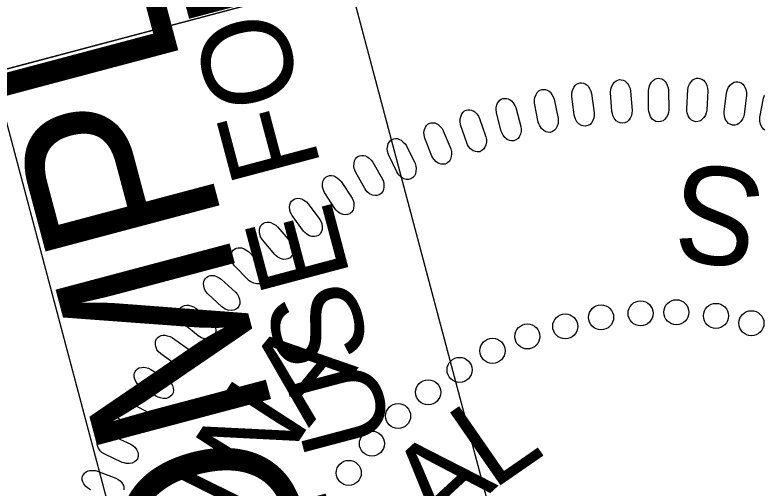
# Model space of a CAD drawing. Extents: x 473963 to 475454, y 503101 to 505009.
# Drawn here: x 474084.44 to 474132.36, y 504611.93 to 504642.22 of the extents above; entities that cross this region are included whole.
import ezdxf

# ---------------------------------------------------------------- set-up
doc = ezdxf.new("R2010")
doc.units = 0
for name, color, linetype in [('Prop PHM Label Text', 7, 'Continuous'), ('Scratch_Level_2', 7, 'Continuous'), ('Scratch_Level_4', 7, 'Continuous')]:
    doc.layers.add(name, color=color, linetype=linetype)

msp = doc.modelspace()

# ---------------------------------------------------------------- linework, layer by layer
at = {"layer": 'Prop PHM Label Text'}
msp.add_line((474051.4, 504630.133), (474160.089, 504659.021), dxfattribs=at)
for points in [[(474051.4, 504630.133), (474025.716, 504726.765), (474134.453, 504755.666), (474160.141, 504659.021)], [(474077.089, 504533.437), (474051.4, 504630.133), (474160.141, 504659.021), (474185.802, 504562.331)]]:
    msp.add_lwpolyline(points, close=True, dxfattribs=at)
at = {"layer": 'Scratch_Level_2'}
msp.add_lwpolyline([(474124.636, 504573.539), (474101.924, 504567.506), (474064.181, 504709.577), (474086.893, 504715.611)], close=True, dxfattribs=at)
at = {"layer": 'Scratch_Level_4'}
for points in [[(474122.636, 504636.032), (474122.549, 504637.256), (474122.571, 504637.477), (474122.612, 504637.62), (474122.713, 504637.798), (474122.802, 504637.914), (474122.908, 504638.002), (474123.01, 504638.049), (474123.12, 504638.077), (474123.233, 504638.065), (474123.355, 504638.043), (474123.464, 504637.991), (474123.575, 504637.898), (474123.641, 504637.823), (474123.718, 504637.679), (474123.79, 504637.504), (474123.824, 504637.347), (474123.921, 504636.094), (474123.91, 504635.923), (474123.875, 504635.781), (474123.797, 504635.615), (474123.695, 504635.468), (474123.604, 504635.381), (474123.451, 504635.311), (474123.303, 504635.28), (474123.152, 504635.309), (474123.044, 504635.352), (474122.91, 504635.442), (474122.779, 504635.603), (474122.699, 504635.777), (474122.661, 504635.904)], [(474124.982, 504636.158), (474124.972, 504637.385), (474125.008, 504637.604), (474125.058, 504637.744), (474125.169, 504637.915), (474125.266, 504638.025), (474125.378, 504638.106), (474125.481, 504638.146), (474125.593, 504638.167), (474125.705, 504638.149), (474125.826, 504638.119), (474125.931, 504638.061), (474126.036, 504637.961), (474126.097, 504637.882), (474126.165, 504637.733), (474126.226, 504637.554), (474126.25, 504637.395), (474126.268, 504636.138), (474126.246, 504635.968), (474126.203, 504635.828), (474126.115, 504635.668), (474126.003, 504635.528), (474125.907, 504635.447), (474125.75, 504635.386), (474125.601, 504635.365), (474125.451, 504635.403), (474125.346, 504635.453), (474125.218, 504635.551), (474125.097, 504635.72), (474125.028, 504635.899), (474124.998, 504636.028)], [(474127.416, 504636.212), (474127.483, 504637.437), (474127.533, 504637.654), (474127.592, 504637.791), (474127.714, 504637.954), (474127.816, 504638.058), (474127.933, 504638.132), (474128.04, 504638.166), (474128.152, 504638.179), (474128.263, 504638.153), (474128.382, 504638.116), (474128.482, 504638.052), (474128.581, 504637.946), (474128.637, 504637.863), (474128.695, 504637.71), (474128.746, 504637.528), (474128.76, 504637.367), (474128.698, 504636.112), (474128.666, 504635.944), (474128.613, 504635.807), (474128.516, 504635.652), (474128.396, 504635.519), (474128.295, 504635.445), (474128.135, 504635.394), (474127.983, 504635.382), (474127.837, 504635.43), (474127.735, 504635.486), (474127.614, 504635.592), (474127.504, 504635.768), (474127.446, 504635.951), (474127.424, 504636.082)], [(474120.227, 504635.803), (474120.064, 504637.019), (474120.071, 504637.241), (474120.104, 504637.387), (474120.193, 504637.57), (474120.275, 504637.692), (474120.375, 504637.785), (474120.473, 504637.839), (474120.582, 504637.873), (474120.695, 504637.869), (474120.818, 504637.855), (474120.93, 504637.81), (474121.047, 504637.725), (474121.117, 504637.654), (474121.204, 504637.514), (474121.286, 504637.345), (474121.33, 504637.189), (474121.505, 504635.945), (474121.505, 504635.773), (474121.479, 504635.629), (474121.412, 504635.46), (474121.319, 504635.306), (474121.234, 504635.214), (474121.086, 504635.134), (474120.941, 504635.094), (474120.787, 504635.114), (474120.677, 504635.149), (474120.537, 504635.231), (474120.397, 504635.383), (474120.305, 504635.552), (474120.259, 504635.677)], [(474129.823, 504636.023), (474129.967, 504637.241), (474130.03, 504637.454), (474130.098, 504637.587), (474130.23, 504637.743), (474130.339, 504637.84), (474130.46, 504637.906), (474130.568, 504637.933), (474130.682, 504637.94), (474130.791, 504637.907), (474130.906, 504637.863), (474131.003, 504637.792), (474131.096, 504637.68), (474131.146, 504637.593), (474131.195, 504637.437), (474131.233, 504637.252), (474131.237, 504637.091), (474131.096, 504635.842), (474131.054, 504635.676), (474130.993, 504635.543), (474130.885, 504635.395), (474130.758, 504635.269), (474130.652, 504635.201), (474130.489, 504635.161), (474130.338, 504635.158), (474130.194, 504635.216), (474130.096, 504635.278), (474129.982, 504635.391), (474129.884, 504635.574), (474129.837, 504635.761), (474129.823, 504635.892)], [(474117.923, 504635.363), (474117.683, 504636.567), (474117.677, 504636.788), (474117.701, 504636.936), (474117.778, 504637.125), (474117.852, 504637.251), (474117.946, 504637.351), (474118.041, 504637.41), (474118.148, 504637.452), (474118.261, 504637.454), (474118.384, 504637.448), (474118.498, 504637.41), (474118.62, 504637.332), (474118.695, 504637.266), (474118.79, 504637.132), (474118.884, 504636.968), (474118.937, 504636.816), (474119.19, 504635.585), (474119.201, 504635.415), (474119.183, 504635.268), (474119.127, 504635.095), (474119.044, 504634.936), (474118.965, 504634.838), (474118.822, 504634.749), (474118.679, 504634.7), (474118.525, 504634.71), (474118.413, 504634.739), (474118.269, 504634.812), (474118.118, 504634.955), (474118.017, 504635.118), (474117.963, 504635.239)], [(474115.555, 504634.769), (474115.241, 504635.955), (474115.221, 504636.176), (474115.235, 504636.324), (474115.3, 504636.517), (474115.366, 504636.648), (474115.454, 504636.754), (474115.545, 504636.819), (474115.649, 504636.867), (474115.762, 504636.877), (474115.885, 504636.878), (474116.001, 504636.847), (474116.128, 504636.778), (474116.207, 504636.716), (474116.31, 504636.589), (474116.414, 504636.431), (474116.476, 504636.282), (474116.806, 504635.069), (474116.828, 504634.9), (474116.82, 504634.753), (474116.774, 504634.576), (474116.702, 504634.413), (474116.628, 504634.31), (474116.492, 504634.212), (474116.352, 504634.155), (474116.198, 504634.155), (474116.084, 504634.176), (474115.935, 504634.24), (474115.777, 504634.374), (474115.665, 504634.53), (474115.603, 504634.647)], [(474113.341, 504634.026), (474112.954, 504635.19), (474112.92, 504635.41), (474112.924, 504635.558), (474112.977, 504635.755), (474113.035, 504635.89), (474113.116, 504636.001), (474113.203, 504636.071), (474113.303, 504636.126), (474113.415, 504636.143), (474113.538, 504636.152), (474113.656, 504636.129), (474113.787, 504636.067), (474113.869, 504636.01), (474113.981, 504635.89), (474114.094, 504635.739), (474114.166, 504635.595), (474114.571, 504634.405), (474114.603, 504634.237), (474114.604, 504634.09), (474114.57, 504633.91), (474114.508, 504633.743), (474114.441, 504633.636), (474114.311, 504633.53), (474114.175, 504633.463), (474114.021, 504633.454), (474113.906, 504633.468), (474113.754, 504633.523), (474113.587, 504633.645), (474113.466, 504633.794), (474113.397, 504633.908)], [(474111.119, 504633.184), (474110.658, 504634.321), (474110.61, 504634.538), (474110.606, 504634.687), (474110.646, 504634.886), (474110.695, 504635.025), (474110.769, 504635.141), (474110.851, 504635.217), (474110.947, 504635.277), (474111.059, 504635.301), (474111.181, 504635.318), (474111.301, 504635.302), (474111.435, 504635.249), (474111.52, 504635.198), (474111.639, 504635.084), (474111.762, 504634.94), (474111.843, 504634.801), (474112.322, 504633.639), (474112.364, 504633.473), (474112.375, 504633.327), (474112.352, 504633.146), (474112.3, 504632.974), (474112.24, 504632.863), (474112.118, 504632.749), (474111.986, 504632.674), (474111.833, 504632.655), (474111.717, 504632.663), (474111.562, 504632.707), (474111.387, 504632.819), (474111.258, 504632.96), (474111.181, 504633.07)], [(474108.863, 504632.173), (474108.332, 504633.278), (474108.271, 504633.492), (474108.257, 504633.641), (474108.285, 504633.842), (474108.325, 504633.983), (474108.392, 504634.104), (474108.469, 504634.185), (474108.561, 504634.252), (474108.671, 504634.282), (474108.792, 504634.306), (474108.912, 504634.298), (474109.049, 504634.253), (474109.138, 504634.208), (474109.264, 504634.102), (474109.395, 504633.966), (474109.484, 504633.832), (474110.035, 504632.702), (474110.088, 504632.539), (474110.108, 504632.395), (474110.096, 504632.212), (474110.056, 504632.038), (474110.003, 504631.924), (474109.887, 504631.801), (474109.761, 504631.719), (474109.609, 504631.69), (474109.494, 504631.69), (474109.336, 504631.724), (474109.155, 504631.826), (474109.015, 504631.959), (474108.933, 504632.062)], [(474106.815, 504631.101), (474106.217, 504632.171), (474106.142, 504632.38), (474106.119, 504632.528), (474106.133, 504632.731), (474106.165, 504632.875), (474106.224, 504632.999), (474106.295, 504633.084), (474106.384, 504633.157), (474106.491, 504633.195), (474106.61, 504633.227), (474106.73, 504633.226), (474106.871, 504633.19), (474106.962, 504633.149), (474107.093, 504633.052), (474107.234, 504632.924), (474107.331, 504632.796), (474107.952, 504631.704), (474108.015, 504631.545), (474108.044, 504631.401), (474108.044, 504631.218), (474108.015, 504631.042), (474107.969, 504630.924), (474107.861, 504630.795), (474107.74, 504630.705), (474107.59, 504630.667), (474107.475, 504630.659), (474107.315, 504630.684), (474107.128, 504630.773), (474106.982, 504630.897), (474106.892, 504630.996)], [(474104.907, 504629.823), (474104.241, 504630.854), (474104.153, 504631.059), (474104.121, 504631.204), (474104.124, 504631.407), (474104.145, 504631.552), (474104.197, 504631.68), (474104.263, 504631.77), (474104.346, 504631.848), (474104.451, 504631.892), (474104.568, 504631.932), (474104.688, 504631.938), (474104.83, 504631.911), (474104.924, 504631.877), (474105.062, 504631.787), (474105.209, 504631.67), (474105.315, 504631.548), (474106.003, 504630.496), (474106.076, 504630.342), (474106.113, 504630.2), (474106.125, 504630.017), (474106.107, 504629.839), (474106.068, 504629.719), (474105.969, 504629.583), (474105.854, 504629.486), (474105.707, 504629.438), (474105.592, 504629.424), (474105.431, 504629.438), (474105.239, 504629.515), (474105.085, 504629.63), (474104.989, 504629.723)], [(474102.894, 504628.384), (474102.165, 504629.371), (474102.065, 504629.57), (474102.024, 504629.713), (474102.013, 504629.916), (474102.027, 504630.062), (474102.069, 504630.193), (474102.13, 504630.287), (474102.208, 504630.37), (474102.311, 504630.42), (474102.424, 504630.467), (474102.544, 504630.481), (474102.688, 504630.463), (474102.783, 504630.435), (474102.926, 504630.354), (474103.081, 504630.246), (474103.193, 504630.131), (474103.946, 504629.124), (474104.029, 504628.975), (474104.076, 504628.836), (474104.098, 504628.654), (474104.092, 504628.475), (474104.061, 504628.353), (474103.97, 504628.211), (474103.861, 504628.107), (474103.718, 504628.05), (474103.604, 504628.028), (474103.442, 504628.032), (474103.245, 504628.098), (474103.084, 504628.202), (474102.984, 504628.289)], [(474101.057, 504626.883), (474100.268, 504627.822), (474100.155, 504628.014), (474100.105, 504628.154), (474100.082, 504628.356), (474100.086, 504628.503), (474100.12, 504628.636), (474100.175, 504628.734), (474100.248, 504628.821), (474100.346, 504628.878), (474100.457, 504628.932), (474100.576, 504628.954), (474100.72, 504628.945), (474100.817, 504628.922), (474100.965, 504628.851), (474101.126, 504628.752), (474101.246, 504628.644), (474102.061, 504627.687), (474102.152, 504627.543), (474102.208, 504627.407), (474102.242, 504627.228), (474102.246, 504627.048), (474102.223, 504626.925), (474102.141, 504626.778), (474102.04, 504626.666), (474101.9, 504626.601), (474101.787, 504626.572), (474101.626, 504626.566), (474101.425, 504626.619), (474101.258, 504626.713), (474101.152, 504626.794)], [(474099.328, 504625.278), (474098.481, 504626.165), (474098.357, 504626.35), (474098.298, 504626.486), (474098.262, 504626.687), (474098.257, 504626.833), (474098.283, 504626.969), (474098.332, 504627.07), (474098.399, 504627.161), (474098.494, 504627.224), (474098.601, 504627.285), (474098.717, 504627.315), (474098.862, 504627.315), (474098.96, 504627.298), (474099.113, 504627.236), (474099.28, 504627.147), (474099.406, 504627.048), (474100.279, 504626.144), (474100.38, 504626.005), (474100.444, 504625.873), (474100.489, 504625.696), (474100.504, 504625.518), (474100.489, 504625.393), (474100.417, 504625.241), (474100.322, 504625.124), (474100.187, 504625.049), (474100.077, 504625.013), (474099.916, 504624.997), (474099.712, 504625.038), (474099.539, 504625.121), (474099.428, 504625.194)], [(474097.671, 504623.533), (474096.77, 504624.365), (474096.634, 504624.542), (474096.567, 504624.675), (474096.518, 504624.872), (474096.504, 504625.018), (474096.521, 504625.154), (474096.563, 504625.259), (474096.625, 504625.354), (474096.715, 504625.423), (474096.819, 504625.491), (474096.933, 504625.527), (474097.078, 504625.536), (474097.177, 504625.526), (474097.333, 504625.473), (474097.505, 504625.396), (474097.637, 504625.304), (474098.565, 504624.457), (474098.674, 504624.325), (474098.746, 504624.197), (474098.803, 504624.023), (474098.829, 504623.846), (474098.822, 504623.72), (474098.76, 504623.565), (474098.673, 504623.442), (474098.542, 504623.359), (474098.434, 504623.316), (474098.274, 504623.29), (474098.069, 504623.317), (474097.891, 504623.39), (474097.776, 504623.456)], [(474096.15, 504621.679), (474095.199, 504622.454), (474095.052, 504622.621), (474094.976, 504622.75), (474094.916, 504622.944), (474094.892, 504623.089), (474094.901, 504623.226), (474094.936, 504623.332), (474094.991, 504623.432), (474095.078, 504623.506), (474095.176, 504623.58), (474095.289, 504623.624), (474095.432, 504623.642), (474095.532, 504623.638), (474095.691, 504623.595), (474095.867, 504623.529), (474096.005, 504623.446), (474096.985, 504622.658), (474097.101, 504622.534), (474097.182, 504622.41), (474097.249, 504622.24), (474097.286, 504622.065), (474097.287, 504621.939), (474097.234, 504621.78), (474097.156, 504621.651), (474097.03, 504621.561), (474096.926, 504621.511), (474096.768, 504621.475), (474096.561, 504621.489), (474096.379, 504621.55), (474096.26, 504621.609)], [(474094.763, 504619.8), (474093.765, 504620.513), (474093.608, 504620.672), (474093.525, 504620.795), (474093.452, 504620.985), (474093.42, 504621.128), (474093.42, 504621.265), (474093.448, 504621.374), (474093.497, 504621.477), (474093.579, 504621.556), (474093.673, 504621.636), (474093.782, 504621.687), (474093.924, 504621.714), (474094.024, 504621.716), (474094.185, 504621.683), (474094.365, 504621.628), (474094.508, 504621.554), (474095.535, 504620.829), (474095.66, 504620.712), (474095.748, 504620.594), (474095.825, 504620.429), (474095.874, 504620.256), (474095.882, 504620.131), (474095.84, 504619.968), (474095.769, 504619.835), (474095.649, 504619.737), (474095.548, 504619.681), (474095.393, 504619.635), (474095.186, 504619.636), (474095, 504619.686), (474094.877, 504619.737)], [(474093.489, 504617.794), (474092.449, 504618.443), (474092.283, 504618.591), (474092.191, 504618.709), (474092.107, 504618.894), (474092.065, 504619.034), (474092.057, 504619.171), (474092.078, 504619.282), (474092.12, 504619.388), (474092.197, 504619.472), (474092.286, 504619.558), (474092.391, 504619.615), (474092.531, 504619.651), (474092.631, 504619.659), (474092.793, 504619.637), (474092.977, 504619.593), (474093.125, 504619.528), (474094.195, 504618.869), (474094.327, 504618.76), (474094.422, 504618.648), (474094.509, 504618.488), (474094.569, 504618.319), (474094.585, 504618.194), (474094.553, 504618.029), (474094.491, 504617.892), (474094.378, 504617.786), (474094.28, 504617.724), (474094.128, 504617.668), (474093.921, 504617.657), (474093.733, 504617.695), (474093.607, 504617.738)], [(474092.301, 504615.673), (474091.221, 504616.256), (474091.045, 504616.392), (474090.947, 504616.505), (474090.851, 504616.684), (474090.801, 504616.822), (474090.784, 504616.958), (474090.798, 504617.069), (474090.834, 504617.178), (474090.905, 504617.267), (474090.988, 504617.357), (474091.09, 504617.422), (474091.228, 504617.466), (474091.327, 504617.481), (474091.49, 504617.469), (474091.676, 504617.437), (474091.827, 504617.381), (474092.937, 504616.791), (474093.075, 504616.69), (474093.177, 504616.585), (474093.275, 504616.43), (474093.345, 504616.265), (474093.369, 504616.141), (474093.347, 504615.975), (474093.294, 504615.834), (474093.187, 504615.722), (474093.094, 504615.653), (474092.946, 504615.588), (474092.74, 504615.564), (474092.55, 504615.59), (474092.422, 504615.625)], [(474091.292, 504613.572), (474090.178, 504614.086), (474089.995, 504614.211), (474089.89, 504614.317), (474089.782, 504614.49), (474089.723, 504614.624), (474089.698, 504614.759), (474089.705, 504614.871), (474089.735, 504614.982), (474089.799, 504615.075), (474089.877, 504615.171), (474089.975, 504615.241), (474090.109, 504615.294), (474090.207, 504615.315), (474090.371, 504615.313), (474090.559, 504615.293), (474090.713, 504615.247), (474091.857, 504614.727), (474092.002, 504614.636), (474092.11, 504614.537), (474092.217, 504614.389), (474092.298, 504614.228), (474092.33, 504614.106), (474092.318, 504613.939), (474092.273, 504613.795), (474092.175, 504613.676), (474092.086, 504613.602), (474091.942, 504613.528), (474091.738, 504613.491), (474091.546, 504613.504), (474091.416, 504613.532)]]:
    msp.add_lwpolyline(points, close=True, dxfattribs=at)
for points in [[(474132.427, 504634.846), (474132.332, 504634.915), (474132.225, 504635.035), (474132.138, 504635.224), (474132.104, 504635.412), (474132.098, 504635.545), (474132.107, 504635.675), (474132.327, 504636.882), (474132.404, 504637.091)], [(474089.266, 504611.82), (474089.074, 504611.934), (474088.963, 504612.033), (474088.845, 504612.199), (474088.778, 504612.329), (474088.744, 504612.462), (474088.745, 504612.575), (474088.766, 504612.686), (474088.825, 504612.784), (474088.897, 504612.884), (474088.99, 504612.96), (474089.121, 504613.022), (474089.217, 504613.049), (474089.381, 504613.058), (474089.57, 504613.049), (474089.727, 504613.012), (474090.901, 504612.566), (474091.051, 504612.483), (474091.166, 504612.391), (474091.282, 504612.251), (474091.372, 504612.096), (474091.411, 504611.976), (474091.41, 504611.808)]]:
    msp.add_lwpolyline(points, dxfattribs=at)
for centre in [(474121.939, 504622.856), (474124.467, 504623.114), (474126.756, 504623.186), (474129.291, 504622.953), (474131.559, 504622.483), (474119.647, 504622.278), (474117.221, 504621.634), (474114.992, 504620.713), (474112.884, 504619.495), (474110.875, 504618.056), (474108.951, 504616.538), (474107.276, 504614.776), (474105.795, 504612.9)]:
    msp.add_circle(centre, 0.801, dxfattribs=at)

# ---------------------------------------------------------------- texts
at = {"layer": 'Scratch_Level_2'}
for s, height, p in [('INCOMPLETE PLANS', 11.52, (474111.031, 504579.185)), ('DO NOT USE FOR R/W ACQUISITION', 5.76, (474116.913, 504584.111))]:
    msp.add_text(s, height=height, rotation=104.8779, dxfattribs=at).set_placement(p)
at = {"layer": 'Scratch_Level_4'}
for s, height, rotation, p in [('S', 6.236, 172.2073, (474132.627, 504632.063)), ('A', 5.669, 50.5507, (474103.236, 504615.757)), ('N', 5.669, 57.04, (474100.435, 504611.578)), ('L', 5.669, 34.7087, (474114.992, 504611.75)), ('A', 5.669, 42.6485, (474111.677, 504608.672)), ('I', 5.669, 63.5294, (474099.526, 504609.469))]:
    msp.add_text(s, height=height, rotation=rotation, dxfattribs=at).set_placement(p)

doc.saveas('drawing.dxf')
